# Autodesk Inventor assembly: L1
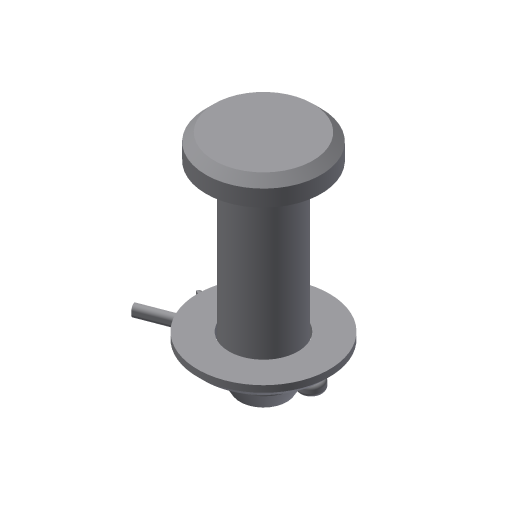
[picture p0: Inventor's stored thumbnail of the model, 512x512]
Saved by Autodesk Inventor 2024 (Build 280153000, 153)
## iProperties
Created: 2023-03
Part Number: L1
Document SubType Name: Zespół
Designer: Andrzej Jaskulski
Checked By: A.J.
Engr Approved By: Andrzej Jaskulski
Mfg Approved By: Andrzej Jaskulski
Authority: A.J.
Company: ATC
Control State: 0
Master: False
Checked Out: False
Shininess: 64.0
Angle Display Precision: 2
Document Length Units: 11269
Document Angle Units: 11279
Document Time Units: 11290
Document Mass Units: 11283
Document Length Units Precision: 3
Document Angle Units Precision: 2
Density: 0.0
Volumn: 0.0
Area: 0.0
PropertySet Name: Model Information
Title: A.J.: Kurs R2024-MEP
Author: Andrzej Jaskulski
Revision Number: 1/24
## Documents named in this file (4)
- C:\Users\AndJas\Documents\R2024-MEP\Obszar roboczy\L1.iam
- C:\Users\AndJas\Documents\R2024-MEP\Pliki Content Center\local.ISO.90.340.8-AJ-Z.ipt
- C:\Users\AndJas\Documents\R2024-MEP\Pliki Content Center\local.ISO.63.30.8-AJ-P.ipt
- C:\Users\AndJas\Documents\R2024-MEP\Pliki Content Center\local.ISO.95.66.8-AJ-S.ipt
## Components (3 placed, 3 different names)
1. ISO 2341  B B - 8 x 24-AJ-S — Zestawiający:1, Zestawiający:2, Zestawiający:3, Zestawiający:4
2. ISO 7090 8 - 140 HV-AJ-P — Zestawiający:1, Zestawiający:4
3. ISO 1234 1.6 x 14 AJ-Z — Zestawiający:2, Zestawiający:3
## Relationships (4: Mate 4)
- Zestawiający:1 [Mate]: ISO 2341  B B - 8 x 24-AJ-S ↔ ISO 7090 8 - 140 HV-AJ-P
- Zestawiający:2 [Mate]: ISO 2341  B B - 8 x 24-AJ-S ↔ ISO 1234 1.6 x 14 AJ-Z
- Zestawiający:3 [Mate]: ISO 2341  B B - 8 x 24-AJ-S ↔ ISO 1234 1.6 x 14 AJ-Z
- Zestawiający:4 [Mate]: ISO 2341  B B - 8 x 24-AJ-S ↔ ISO 7090 8 - 140 HV-AJ-P
